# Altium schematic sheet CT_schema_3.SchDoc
size 298 x 230 mm
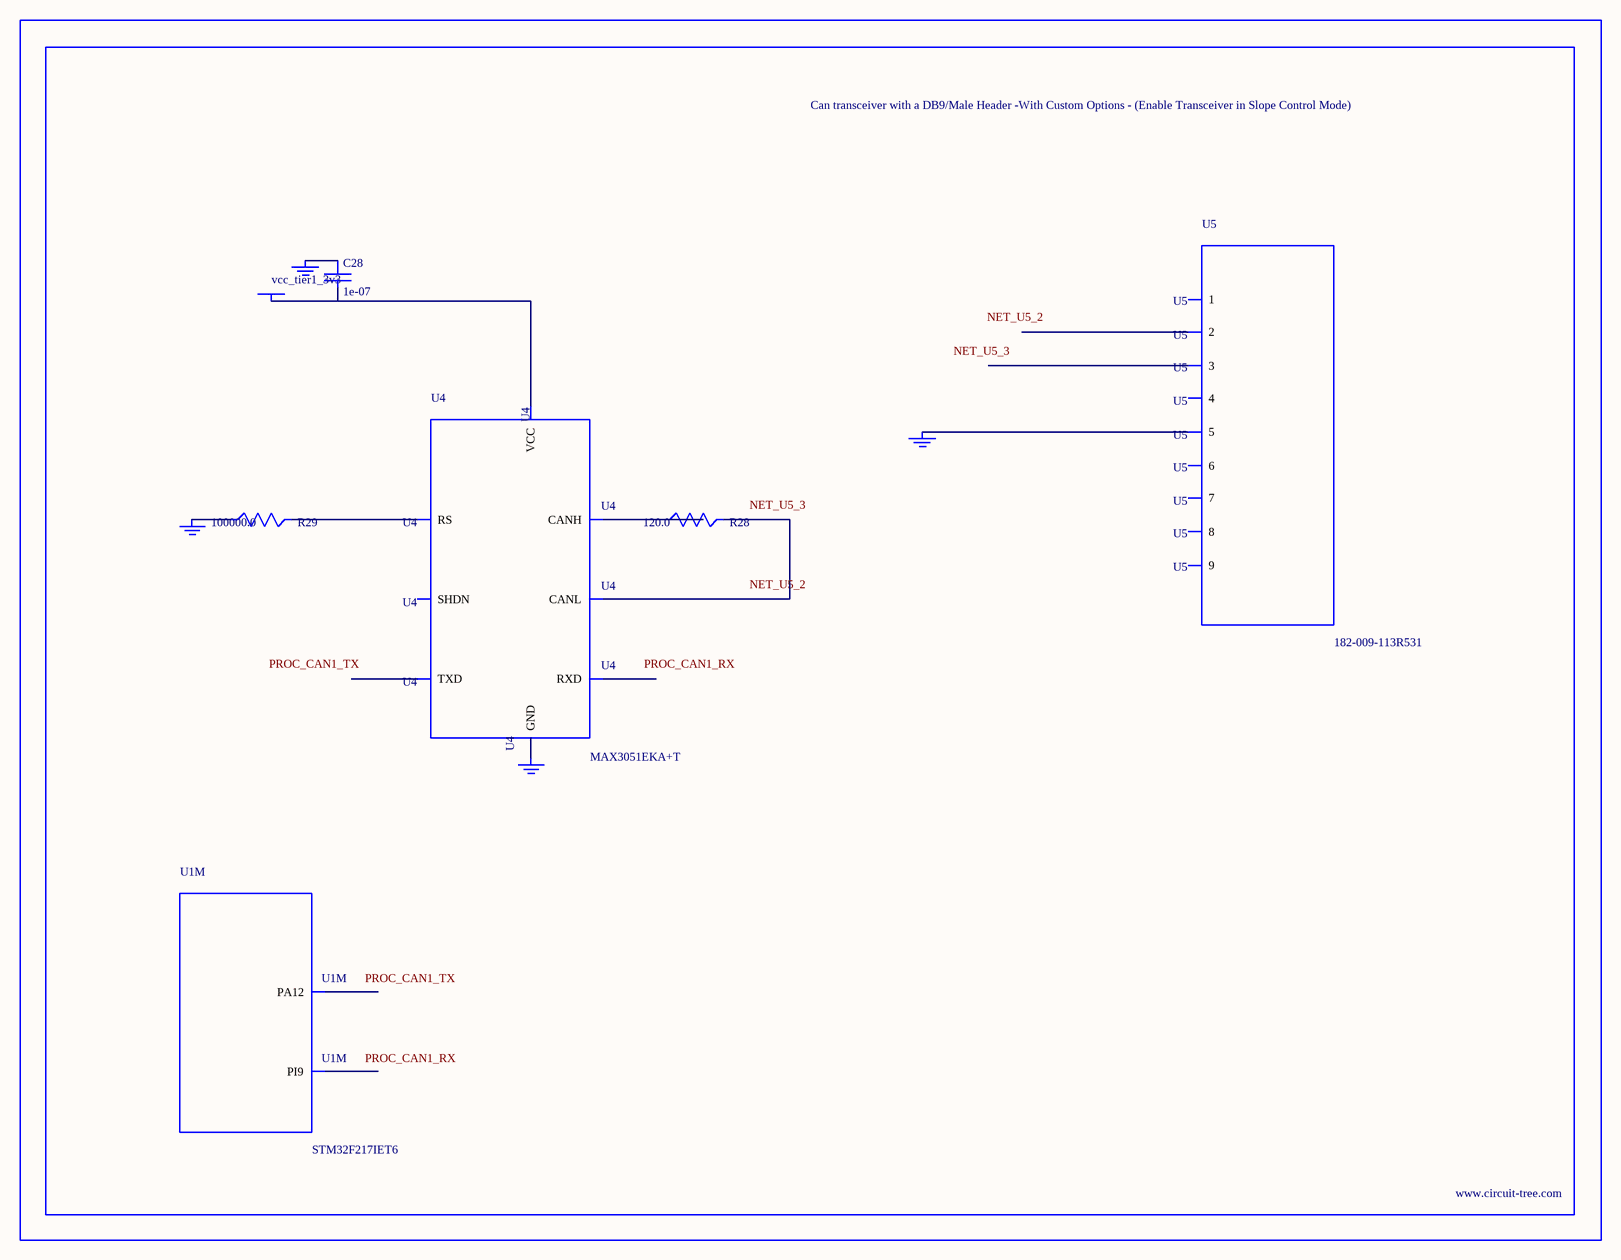
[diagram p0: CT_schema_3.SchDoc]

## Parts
BORDER2  (no value)
C28  1e-07  [C0402]
GND_INSTANCE_2_0  (no value)
GND_INSTANCE_2_1  (no value)
GND_INSTANCE_2_2  (no value)
GND_INSTANCE_2_3  (no value)
POWER_INSTANCE_2_0  vcc_tier1_3v3
R28  120.0  [R0603]
R29  100000.0  [R0603]
U1  STM32F217IET6  [LQFP176]  (part M of 14)
U4  MAX3051EKA+T  [SOT-23-8]
U5  182-009-113R531  [182-009-MALE]

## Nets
NetC28_1: C28.1 GND_INSTANCE_2_0.0(GND)
NetC28_2: C28.2 POWER_INSTANCE_2_0.0(PWR) U4.3(VCC)
NetGND_INSTANCE_2_1_0: GND_INSTANCE_2_1.0(GND) R29.1
NetGND_INSTANCE_2_2_0: GND_INSTANCE_2_2.0(GND) U4.2(GND)
NetGND_INSTANCE_2_3_0: GND_INSTANCE_2_3.0(GND) U5.5
NetR28_1: R28.1 U4.7(CANH)
NetR28_2: R28.2 U4.6(CANL)
NetR29_2: R29.2 U4.8(RS)

Not connected (* = marked no-connect by the designer): U1 11(PI9) 123(PA12); U4 1(TXD) 4(RXD) 5(SHDN); U5 1 2 3 4 6 7 8 9

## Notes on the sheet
- Labels drawn without touching a wire or pin: NET_U5_2, NET_U5_3, PROC_CAN1_RX, PROC_CAN1_TX

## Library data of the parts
BORDER2 = BORDER_PAGE2
C28 = C0402C104K3RACTU
GND_INSTANCE_2_0-GND_INSTANCE_2_3 = GND
POWER_INSTANCE_2_0 = PWR
R28 = RC0603JR-07120RL
R29 = RC0603JR-07100KL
